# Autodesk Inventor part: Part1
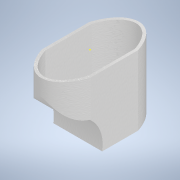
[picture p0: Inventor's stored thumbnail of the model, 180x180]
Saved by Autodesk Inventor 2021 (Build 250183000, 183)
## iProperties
Created: 2023-08
Part Number: Part1
Material: Aluminum 7075
Document SubType Name: Modeling
Designer: canad
Density: 2.81 g/cm^3
Appearance: Satin - Brushed Heavy
Author: canad
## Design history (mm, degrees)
sketch "Sketch1"
  geometry: L1 (0, 0)-(0, -350); L2 (0, 0)-(0, 350); L3 (0, -350)-(-500, -350); L4 (-500, -350)-(-500, 0); L5 (-500, 0)-(-500, 87.5); A1 r 202.795 centre (-59.409, 156.102) between (0, 350) and (-261.322, 175); A2 r 259.713 centre (-458.617, 343.895) between (-500, 87.5) and (-261.322, 175)
  constraints: 10 end point, 4 point on circle, 2 centre point, 2 vertical
  dimensions: "d0" = 350 distance of L1.start L1.end; "d1" = 350 distance of L1.start L2.end; "d2" = 500 distance of L1.start L4.end; "d3" = 500 distance of L1.end L3.end; "d4" = 87.5 distance of L4.end L5.end
sketch "Sketch3" dims "d5" = 350, "d10" = 200
  geometry: 3 further points; 2 other entities
  constraints: 2 coincident, 4 other
extrude "Extrusion2" new body sketch "Sketch3" distance "d11" = 500; taper "d12" = 0 deg
extrude "Extrusion3" sketch "Sketch1" stored distance "d13" = 350; taper "d14" = 0 deg
sketch "Sketch5"
  geometry: 1 further point
shell "Shell1" dims "d15" = 20
sketch "Sketch6"
  geometry: C1 r 87.816 at (11.113, -166.688); C2 r 10 at (74.612, -169.863); C3 r 10 at (14.287, -107.95); C4 r 10 at (14.287, -228.6); C5 r 10 at (-46.037, -168.275); 1 further point
  constraints: 5 centre point
  dimensions: "d16" = 20 diameter of C2; "d17" = 20 diameter of C3; "d18" = 20 diameter of C4; "d19" = 20 diameter of C5
extrude "Extrusion4" cut sketch "Sketch6" stored distance "d20" = 10; taper "d21" = 0 deg
body "Solid2"
other parameters: "sa_0" = 2.1e+07
